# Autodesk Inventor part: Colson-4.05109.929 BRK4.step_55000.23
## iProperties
Created: 2010-10
Part Number: Colson-4.05109.929 BRK4.step_55000.23
Document SubType Name: Modeling
Designer: Administrator
Density: 7.85 g/cm^3
Material: Steel
Mass: 192.232 g
Surface Area: 96.2959 cm^2
Volume: 24.4881 cm^3
Author: Administrator
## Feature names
1. Base1
